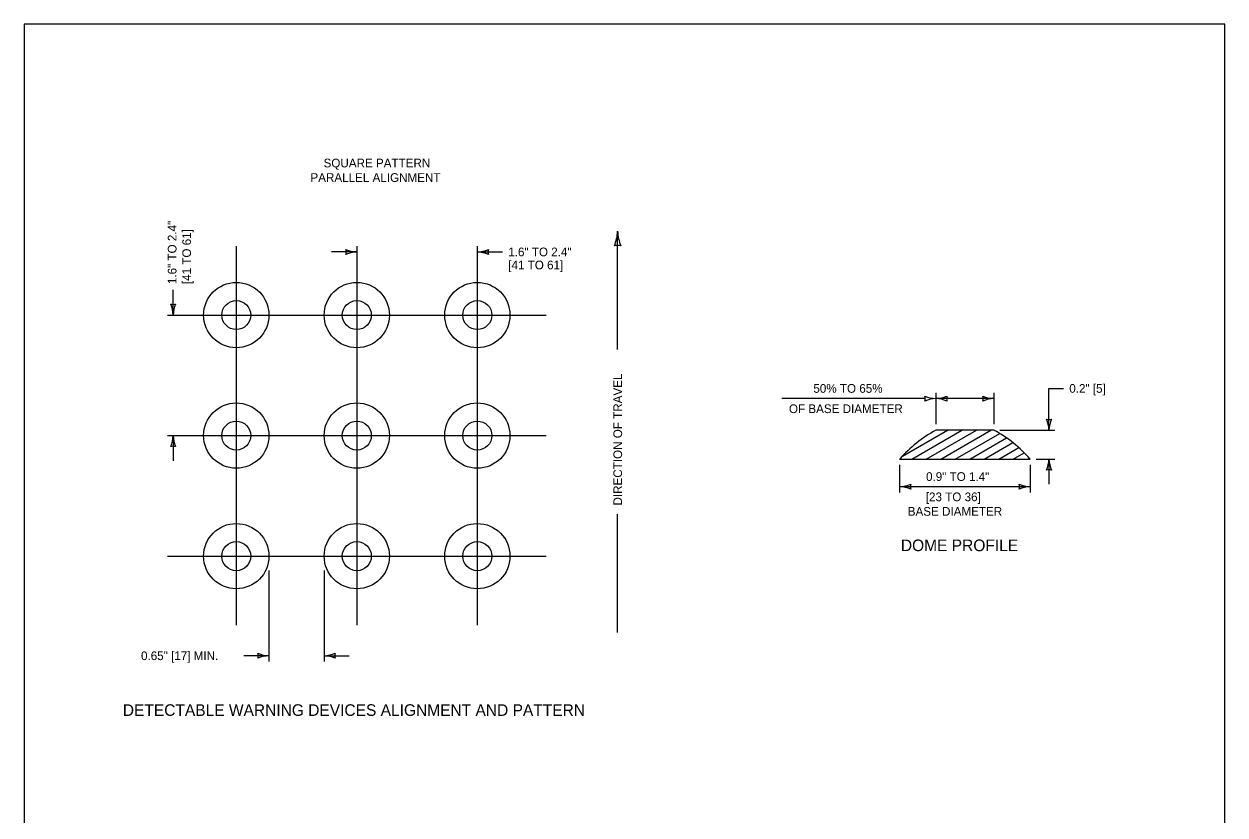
# Model space of a CAD drawing. Extents: x 49991.4 to 50021, y 49987.6 to 50011.4.
# Drawn here: x 50000.34 to 50008.61, y 50005.81 to 50011.26 of the extents above; entities that cross this region are included whole.
import ezdxf

# ---------------------------------------------------------------- set-up
doc = ezdxf.new("R2010")
doc.units = 0
for name, color, linetype in [('Level 1', 7, 'Continuous'), ('Level 2', 7, 'Continuous'), ('Level 3', 7, 'Continuous'), ('Level 5', 7, 'Continuous')]:
    doc.layers.add(name, color=color, linetype=linetype)

msp = doc.modelspace()

# ---------------------------------------------------------------- linework, layer by layer
at = {"layer": 'Level 1'}
for p, q in [((50006.3905, 50008.2844), (50006.7013, 50008.4638)), ((50006.4549, 50008.2638), (50006.8013, 50008.4638)), ((50006.5549, 50008.2638), (50006.9013, 50008.4638)), ((50007.022, 50008.4638), (50006.622, 50008.4638)), ((50006.6549, 50008.2638), (50007.0013, 50008.4638)), ((50006.7549, 50008.2638), (50007.0617, 50008.4409)), ((50006.8549, 50008.2638), (50007.1087, 50008.4103)), ((50006.9549, 50008.2638), (50007.1524, 50008.3778)), ((50007.0549, 50008.2638), (50007.1931, 50008.3436)), ((50007.1549, 50008.2638), (50007.231, 50008.3077)), ((50006.372, 50008.2638), (50007.272, 50008.2638)), ((50007.2549, 50008.2638), (50007.2662, 50008.2703))]:
    msp.add_line(p, q, dxfattribs=at)
msp.add_lwpolyline([(50008.6146, 50011.2628), (50000.3356, 50011.2628), (50000.3356, 50000.0624), (50008.6146, 50000.0624)], close=True, dxfattribs=at)
for centre, radius in [((50001.7988, 50009.2569), 0.225), ((50002.6297, 50009.2569), 0.225), ((50003.4605, 50009.2569), 0.225), ((50001.7988, 50009.2568), 0.1), ((50002.6296, 50009.2568), 0.1), ((50003.4605, 50009.2568), 0.1), ((50001.7988, 50008.4261), 0.225), ((50002.6297, 50008.4261), 0.225), ((50003.4605, 50008.4261), 0.225), ((50001.7988, 50008.426), 0.1), ((50002.6297, 50008.426), 0.1), ((50003.4605, 50008.426), 0.1), ((50001.7988, 50007.5952), 0.225), ((50002.6297, 50007.5952), 0.225), ((50003.4605, 50007.5952), 0.225), ((50001.7988, 50007.5951), 0.1), ((50002.6297, 50007.5951), 0.1), ((50003.4605, 50007.5951), 0.1), ((50003.4605, 50007.5951), 0.1)]:
    msp.add_circle(centre, radius, dxfattribs=at)
for centre, start, end in [((50007.0503, 50007.6722), 118.41441, 138.90521), ((50006.5937, 50007.6722), 41.09479, 61.58559)]:
    msp.add_arc(centre, 0.9, start, end, dxfattribs=at)
at = {"layer": 'Level 3'}
for p, q in [((50004.4276, 50009.0189), (50004.4276, 50009.8344)), ((50002.6297, 50009.6919), (50002.4563, 50009.6919)), ((50003.4605, 50009.6919), (50003.6339, 50009.6919)), ((50001.3638, 50009.2568), (50001.3638, 50009.4302)), ((50006.622, 50008.7213), (50006.622, 50008.5038)), ((50007.022, 50008.7213), (50007.022, 50008.5038)), ((50007.4012, 50008.4638), (50007.4012, 50008.7513)), ((50007.4012, 50008.7513), (50007.5012, 50008.7513)), ((50006.5485, 50008.6813), (50005.5598, 50008.6813)), ((50007.022, 50008.6813), (50006.6218, 50008.6813)), ((50001.3638, 50008.426), (50001.3638, 50008.2526)), ((50007.062, 50008.4638), (50007.4412, 50008.4638)), ((50006.372, 50008.2238), (50006.372, 50008.0338)), ((50007.272, 50008.2238), (50007.272, 50008.0338)), ((50007.312, 50008.2638), (50007.4412, 50008.2638)), ((50007.4012, 50008.2638), (50007.4012, 50008.0904)), ((50007.272, 50008.0738), (50006.372, 50008.0738)), ((50004.4276, 50007.0695), (50004.4276, 50007.8849)), ((50002.0238, 50007.4952), (50002.0238, 50006.9087)), ((50002.4047, 50007.4952), (50002.4047, 50006.8687)), ((50002.0238, 50006.9087), (50001.8504, 50006.9087)), ((50002.0238, 50006.9087), (50002.0238, 50006.8687)), ((50002.4047, 50006.9087), (50002.5781, 50006.9087))]:
    msp.add_line(p, q, dxfattribs=at)
for centre, radius, start, end in [((50004.1315, 50009.8466), 0.2964, 337.45601, 357.63952), ((50004.7379, 50009.8497), 0.3107, 182.82731, 202.07716), ((50004.4276, 50009.6634), 0.073, 72.13882, 107.86118), ((50002.6388, 50009.9141), 0.2223, 247.45601, 267.63952), ((50002.5015, 50009.6919), 0.0548, 342.13882, 17.86118), ((50002.6412, 50009.4592), 0.233, 92.82731, 112.07716), ((50003.449, 50009.9247), 0.233, 272.82731, 292.07716), ((50003.4514, 50009.4698), 0.2223, 67.45601, 87.63952), ((50003.5888, 50009.6919), 0.0548, 162.13882, 197.86118), ((50001.3638, 50009.3851), 0.0548, 252.13882, 287.86118), ((50001.1311, 50009.2454), 0.233, 2.82731, 22.07716), ((50001.586, 50009.2477), 0.2223, 157.45601, 177.63952), ((50006.6311, 50008.9035), 0.2223, 247.45601, 267.63952), ((50006.4937, 50008.6813), 0.0548, 342.13882, 17.86118), ((50006.6334, 50008.4486), 0.233, 92.82731, 112.07716), ((50006.6105, 50008.914), 0.233, 272.82731, 292.07716), ((50006.6128, 50008.4592), 0.2223, 67.45601, 87.63952), ((50006.7502, 50008.6813), 0.0548, 162.13882, 197.86118), ((50007.0311, 50008.9035), 0.2223, 247.45601, 267.63952), ((50006.8937, 50008.6813), 0.0548, 342.13882, 17.86118), ((50007.0334, 50008.4486), 0.233, 92.82731, 112.07716), ((50007.4012, 50008.592), 0.0548, 252.13882, 287.86118), ((50007.1685, 50008.4523), 0.233, 2.82731, 22.07716), ((50007.6233, 50008.4546), 0.2223, 157.45601, 177.63952), ((50001.1417, 50008.4352), 0.2223, 337.45601, 357.63952), ((50001.5966, 50008.4375), 0.233, 182.82731, 202.07716), ((50001.3638, 50008.2978), 0.0548, 72.13882, 107.86118), ((50007.1791, 50008.2729), 0.2223, 337.45601, 357.63952), ((50007.6339, 50008.2753), 0.233, 182.82731, 202.07716), ((50007.4012, 50008.1356), 0.0548, 72.13882, 107.86118), ((50006.3605, 50008.3065), 0.233, 272.82731, 292.07716), ((50006.3628, 50007.8516), 0.2223, 67.45601, 87.63952), ((50006.5002, 50008.0738), 0.0548, 162.13882, 197.86118), ((50007.2812, 50008.2959), 0.2223, 247.45601, 267.63952), ((50007.1438, 50008.0738), 0.0548, 342.13882, 17.86118), ((50007.2835, 50007.8411), 0.233, 92.82731, 112.07716), ((50002.033, 50007.1308), 0.2223, 247.45601, 267.63952), ((50001.8956, 50006.9087), 0.0548, 342.13882, 17.86118), ((50002.0353, 50006.676), 0.233, 92.82731, 112.07716), ((50002.3932, 50007.1414), 0.233, 272.82731, 292.07716), ((50002.3955, 50006.6865), 0.2223, 67.45601, 87.63952), ((50002.5329, 50006.9087), 0.0548, 162.13882, 197.86118)]:
    msp.add_arc(centre, radius, start, end, dxfattribs=at)
at = {"layer": 'Level 5'}
for p, q in [((50001.7988, 50009.7319), (50001.7988, 50007.1202)), ((50002.6297, 50009.7319), (50002.6297, 50007.1202)), ((50003.4605, 50009.7319), (50003.4605, 50007.1202)), ((50001.3238, 50009.2568), (50003.9355, 50009.2568)), ((50001.3238, 50008.426), (50003.9355, 50008.426)), ((50001.3238, 50007.5951), (50003.9355, 50007.5951))]:
    msp.add_line(p, q, dxfattribs=at)

# ---------------------------------------------------------------- texts
at = {"layer": 'Level 2'}
for s, height, p in [('SQUARE PATTERN', 0.06, (50002.4006, 50010.2747)), ('PARALLEL ALIGNMENT', 0.06, (50002.3102, 50010.1747)), ('1.6" TO 2.4"', 0.06, (50003.6739, 50009.6619)), ('[41 TO 61]', 0.06, (50003.6739, 50009.5719)), ('50% TO 65%', 0.06, (50005.7771, 50008.7213)), ('0.2" [5]', 0.06, (50007.5412, 50008.7213)), ('OF BASE DIAMETER', 0.06, (50005.6089, 50008.5813)), ('0.9" TO 1.4"', 0.06, (50006.5538, 50008.1136)), ('[23 TO 36]', 0.06, (50006.5521, 50007.9738)), ('BASE DIAMETER', 0.06, (50006.4278, 50007.8738)), ('DOME PROFILE', 0.08, (50006.3804, 50007.6297)), ('0.65" [17] MIN.', 0.06, (50001.1421, 50006.8787)), ('DETECTABLE WARNING DEVICES ALIGNMENT AND PATTERN', 0.08, (50001.0168, 50006.4942))]:
    msp.add_text(s, height=height, dxfattribs=at).set_placement(p)
for s, p in [('1.6" TO 2.4"', (50001.3867, 50009.4702)), ('[41 TO 61]', (50001.4867, 50009.4702)), ('DIRECTION OF TRAVEL', (50004.4584, 50007.9442))]:
    msp.add_text(s, height=0.06, rotation=90, dxfattribs=at).set_placement(p)

doc.saveas('drawing.dxf')
